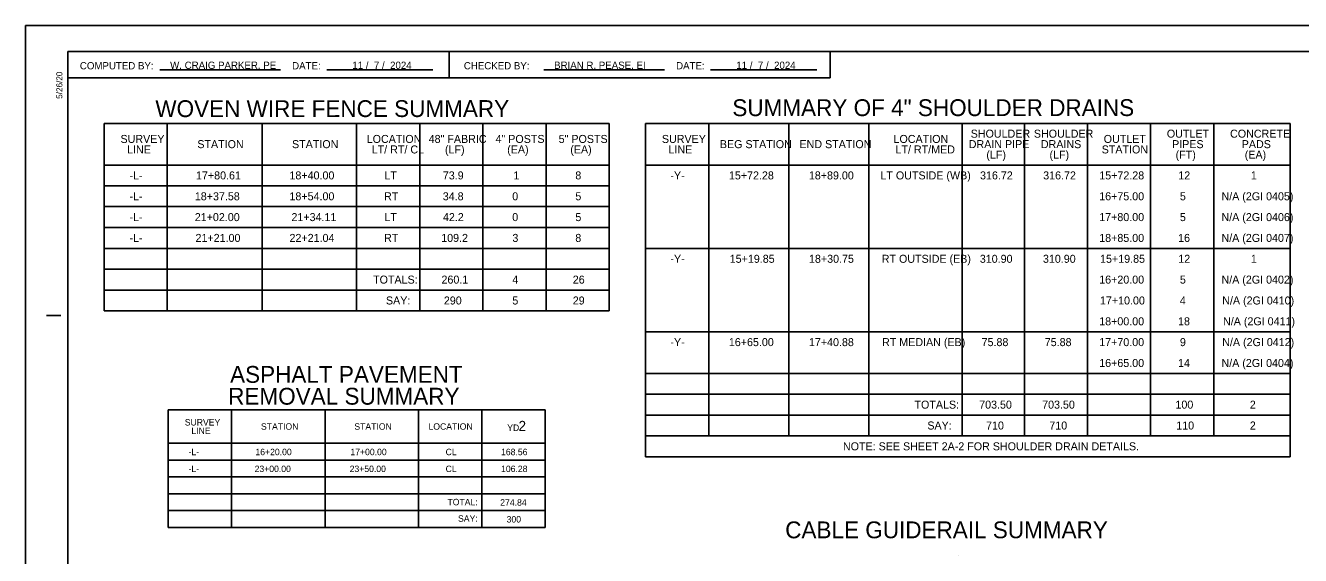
# Model space of a CAD drawing. Extents: x 1551694 to 1553358, y 810412 to 811095.
# Drawn here: x 1552983.2 to 1553203.1, y 810610.5 to 810701.9 of the extents above; entities that cross this region are included whole.
import ezdxf

# ---------------------------------------------------------------- set-up
doc = ezdxf.new("R2010")
doc.units = 0
for name, color, linetype in [('Construction Elements LEVEL', 7, 'Continuous'), ('Default', 7, 'Continuous'), ('Drop Inlet Grate 2 Narrow Slot and Flat Grates 840 29 36 Dia BD-Top CELL', 7, 'Continuous'), ('Drop Inlet Grate 2 Narrow Slot and Flat Grates 840 29 36 Dia TB-Top CELL', 7, 'Continuous'), ('E_NCDOT_Vertical_Profile_Ground_Line', 7, 'Continuous'), ('P_HYD_Pipe_RCP_15in_Class_III', 7, 'Continuous'), ('V Ditch Special Lateral with PSRM Detail CELL', 7, 'Continuous')]:
    doc.layers.add(name, color=color, linetype=linetype)

msp = doc.modelspace()

# ---------------------------------------------------------------- linework, layer by layer
at = {"layer": 'Construction Elements LEVEL'}
for p, q in [((1552996.77, 810685.06), (1553083.88, 810685.06)), ((1552996.77, 810685.06), (1552996.77, 810652.72)), ((1553007.66, 810685.06), (1553007.66, 810652.72)), ((1553024, 810685.06), (1553024, 810652.72)), ((1553040.32, 810685.06), (1553040.32, 810652.72)), ((1553051.21, 810685.06), (1553051.21, 810652.72)), ((1553062.1, 810685.06), (1553062.1, 810652.72)), ((1553072.99, 810685.06), (1553072.99, 810652.72)), ((1553083.88, 810685.06), (1553083.88, 810652.72)), ((1553090.15, 810685.06), (1553201.33, 810685.06)), ((1553090.15, 810685.06), (1553090.15, 810627.56)), ((1553101.04, 810685.06), (1553101.04, 810631.15)), ((1553114.84, 810685.06), (1553114.84, 810631.15)), ((1553128.64, 810685.06), (1553128.64, 810631.15)), ((1553144.74, 810685.06), (1553144.74, 810631.15)), ((1553155.47, 810685.06), (1553155.47, 810631.15)), ((1553166.36, 810685.06), (1553166.36, 810631.15)), ((1553177.25, 810685.06), (1553177.25, 810631.15)), ((1553188.14, 810685.06), (1553188.14, 810631.15)), ((1553201.33, 810685.06), (1553201.33, 810627.56)), ((1552996.77, 810677.87), (1553083.88, 810677.87)), ((1553090.15, 810677.87), (1553201.33, 810677.87)), ((1552996.77, 810674.28), (1553083.88, 810674.28)), ((1552996.77, 810670.69), (1553083.88, 810670.69)), ((1552996.77, 810670.69), (1553083.88, 810670.69)), ((1552996.77, 810667.09), (1553083.88, 810667.09)), ((1552996.77, 810663.5), (1553083.88, 810663.5)), ((1553090.15, 810663.5), (1553201.33, 810663.5)), ((1553090.15, 810663.5), (1553201.33, 810663.5)), ((1552996.77, 810659.9), (1553083.88, 810659.9)), ((1552996.77, 810656.31), (1553083.88, 810656.31)), ((1552996.77, 810652.72), (1553083.88, 810652.72)), ((1552996.77, 810652.72), (1553083.88, 810652.72)), ((1553090.15, 810649.12), (1553201.33, 810649.12)), ((1553090.15, 810641.94), (1553201.33, 810641.94)), ((1553090.15, 810638.34), (1553201.33, 810638.34)), ((1553007.84, 810635.68), (1553072.81, 810635.68)), ((1553007.84, 810635.68), (1553007.84, 810615.37)), ((1553018.76, 810635.68), (1553018.76, 810615.37)), ((1553034.86, 810635.68), (1553034.86, 810615.37)), ((1553050.96, 810635.68), (1553050.96, 810615.37)), ((1553061.89, 810635.68), (1553061.89, 810615.37)), ((1553072.81, 810635.68), (1553072.81, 810615.37)), ((1553090.15, 810634.75), (1553201.33, 810634.75)), ((1553007.84, 810629.88), (1553072.81, 810629.88)), ((1553090.15, 810631.15), (1553201.33, 810631.15)), ((1553090.15, 810627.56), (1553201.33, 810627.56)), ((1553007.84, 810626.98), (1553072.81, 810626.98)), ((1553007.84, 810624.07), (1553072.81, 810624.07)), ((1553007.84, 810621.17), (1553072.81, 810621.17)), ((1553007.84, 810618.27), (1553072.81, 810618.27)), ((1553007.84, 810615.37), (1553072.81, 810615.37))]:
    msp.add_line(p, q, dxfattribs=at)
at = {"layer": 'Drop Inlet Grate 2 Narrow Slot and Flat Grates 840 29 36 Dia TB-Top CELL'}
for p, q in [((1553056.25, 810692.88), (1553056.25, 810697.43)), ((1553122.01, 810692.88), (1553122.01, 810697.43)), ((1553006.39, 810694.26), (1553027.21, 810694.26)), ((1553035.15, 810694.26), (1553053.44, 810694.26)), ((1553072.61, 810694.26), (1553093.43, 810694.26)), ((1553101.37, 810694.26), (1553119.66, 810694.26)), ((1553122.01, 810692.88), (1552990.5, 810692.88))]:
    msp.add_line(p, q, dxfattribs=at)
at = {"layer": 'E_NCDOT_Vertical_Profile_Ground_Line'}
for p, q in [((1553029.57, 810685.05), (1553029.57, 810685.05)), ((1553031.02, 810685.02), (1553031.02, 810685.02)), ((1553033.12, 810685.08), (1553033.12, 810685.08)), ((1553034.42, 810685.05), (1553034.42, 810685.05)), ((1553040.63, 810635.67), (1553040.63, 810635.67)), ((1553042.08, 810635.65), (1553042.08, 810635.65)), ((1553044.19, 810635.69), (1553044.19, 810635.69)), ((1553045.49, 810635.67), (1553045.49, 810635.67)), ((1553144.14, 810610.54), (1553144.14, 810610.54))]:
    msp.add_line(p, q, dxfattribs=at)
at = {"layer": 'P_HYD_Pipe_RCP_15in_Class_III'}
for p, q in [((1552990.5, 810486.43), (1552990.5, 810697.43)), ((1553320.5, 810697.43), (1552990.5, 810697.43)), ((1552986.8, 810651.93), (1552989.31, 810651.94))]:
    msp.add_line(p, q, dxfattribs=at)
at = {"layer": 'V Ditch Special Lateral with PSRM Detail CELL'}
for p, q in [((1553323.21, 810701.93), (1552983.21, 810701.93)), ((1552983.21, 810701.93), (1552983.21, 810481.93))]:
    msp.add_line(p, q, dxfattribs=at)

# ---------------------------------------------------------------- texts
at = {"layer": 'Construction Elements LEVEL'}
for s, height, p in [('YD', 1.114, (1553066.29, 810632.01)), ('2', 1.74, (1553068.24, 810632.01))]:
    msp.add_text(s, height=height, dxfattribs=at).set_placement(p)
at = {"layer": 'Default'}
for s, p in [('-L-', (1553001.14, 810675.39)), ('17+80.61', (1553012.61, 810675.39)), ('18+40.00', (1553028.73, 810675.39)), ('LT', (1553045.11, 810675.39)), ('73.9', (1553055.18, 810675.39)), ('1', (1553067.36, 810675.39)), ('8', (1553078.03, 810675.39)), ('-Y-', (1553094.43, 810675.39)), ('15+72.28', (1553104.52, 810675.39)), ('18+89.00', (1553118.31, 810675.39)), ('LT OUTSIDE (WB)', (1553130.65, 810675.39)), ('316.72', (1553147.83, 810675.39)), ('316.72', (1553158.72, 810675.39)), ('15+72.28', (1553168.39, 810675.39)), ('12', (1553182.02, 810675.39)), ('1', (1553194.53, 810675.39)), ('-L-', (1553001.14, 810671.79)), ('18+37.58', (1553012.41, 810671.79)), ('18+54.00', (1553028.73, 810671.79)), ('RT', (1553045.04, 810671.79)), ('34.8', (1553055.17, 810671.79)), ('0', (1553067.15, 810671.79)), ('5', (1553078.04, 810671.79)), ('16+75.00', (1553168.38, 810671.79)), ('5', (1553182.3, 810671.79)), ('N/A (2GI 0405)', (1553189.47, 810671.79)), ('-L-', (1553001.14, 810668.2)), ('21+02.00', (1553012.4, 810668.2)), ('21+34.11', (1553029.07, 810668.2)), ('LT', (1553045.11, 810668.2)), ('42.2', (1553055.2, 810668.2)), ('0', (1553067.15, 810668.2)), ('5', (1553078.04, 810668.2)), ('17+80.00', (1553168.38, 810668.2)), ('5', (1553182.3, 810668.2)), ('N/A (2GI 0406)', (1553189.47, 810668.2)), ('-L-', (1553001.14, 810664.61)), ('21+21.00', (1553012.53, 810664.61)), ('22+21.04', (1553028.74, 810664.61)), ('RT', (1553045.04, 810664.61)), ('109.2', (1553054.9, 810664.61)), ('3', (1553067.18, 810664.61)), ('8', (1553078.03, 810664.61)), ('18+85.00', (1553168.38, 810664.61)), ('16', (1553181.99, 810664.61)), ('N/A (2GI 0407)', (1553189.47, 810664.61)), ('-Y-', (1553094.43, 810661.01)), ('15+19.85', (1553104.66, 810661.01)), ('18+30.75', (1553118.33, 810661.01)), ('RT OUTSIDE (EB)', (1553130.88, 810661.01)), ('310.90', (1553147.79, 810661.01)), ('310.90', (1553158.68, 810661.01)), ('15+19.85', (1553168.53, 810661.01)), ('12', (1553182.02, 810661.01)), ('1', (1553194.53, 810661.01)), ('260.1', (1553054.95, 810657.42)), ('4', (1553067.16, 810657.42)), ('26', (1553077.59, 810657.42)), ('16+20.00', (1553168.38, 810657.42)), ('5', (1553182.3, 810657.42)), ('N/A (2GI 0402)', (1553189.47, 810657.42)), ('290', (1553055.36, 810653.82)), ('5', (1553067.17, 810653.82)), ('29', (1553077.59, 810653.82)), ('17+10.00', (1553168.51, 810653.82)), ('4', (1553182.29, 810653.82)), ('N/A (2GI 0410)', (1553189.6, 810653.82)), ('N/A (2GI 0411)', (1553189.74, 810650.23)), ('18+00.00', (1553168.38, 810650.23)), ('18', (1553181.98, 810650.23)), ('-Y-', (1553094.43, 810646.64)), ('16+65.00', (1553104.51, 810646.64)), ('17+40.88', (1553118.32, 810646.64)), ('RT MEDIAN (EB)', (1553130.93, 810646.64)), ('75.88', (1553148.1, 810646.64)), ('75.88', (1553158.99, 810646.64)), ('17+70.00', (1553168.38, 810646.64)), ('9', (1553182.3, 810646.64)), ('N/A (2GI 0412)', (1553189.6, 810646.64)), ('16+65.00', (1553168.38, 810643.04)), ('14', (1553181.98, 810643.04)), ('N/A (2GI 0404)', (1553189.47, 810643.04)), ('703.50', (1553147.68, 810635.86)), ('703.50', (1553158.54, 810635.86)), ('100', (1553181.53, 810635.86)), ('2', (1553194.36, 810635.86)), ('710', (1553148.87, 810632.26)), ('710', (1553159.78, 810632.26)), ('110', (1553181.67, 810632.26)), ('2', (1553194.36, 810632.26))]:
    msp.add_text(s, height=1.38, rotation=360, dxfattribs=at).set_placement(p)
at = {"layer": 'Drop Inlet Grate 2 Narrow Slot and Flat Grates 840 29 36 Dia BD-Top CELL'}
for s, p in [('W. CRAIG PARKER, PE', (1553008.15, 810694.45)), ('BRIAN R. PEASE, EI', (1553074.37, 810694.45)), ('COMPUTED BY:', (1552992.58, 810694.37)), ('DATE:', (1553029.19, 810694.37)), ('CHECKED BY:', (1553058.8, 810694.37)), ('DATE:', (1553095.41, 810694.37))]:
    msp.add_text(s, height=1.25, dxfattribs=at).set_placement(p)
at = {"layer": 'E_NCDOT_Vertical_Profile_Ground_Line'}
for s, height, p in [('11 /  7 /  2024', 1.25, (1553039.58, 810694.45)), ('11 /  7 /  2024', 1.25, (1553105.8, 810694.45)), ('SURVEY', 1.114, (1553010.67, 810632.95)), ('LINE', 1.114, (1553011.81, 810631.49)), ('STATION', 1.114, (1553023.82, 810632.22)), ('STATION', 1.114, (1553039.92, 810632.22)), ('LOCATION', 1.114, (1553052.71, 810632.22)), ('-L-', 1.114, (1553011.33, 810627.83)), ('16+20.00', 1.114, (1553022.86, 810627.83)), ('17+00.00', 1.114, (1553039.24, 810627.83)), ('CL', 1.114, (1553055.66, 810627.83)), ('168.56', 1.114, (1553065.22, 810627.83)), ('-L-', 1.114, (1553011.33, 810624.92)), ('23+00.00', 1.114, (1553022.72, 810624.92)), ('23+50.00', 1.114, (1553039.11, 810624.92)), ('CL', 1.114, (1553055.66, 810624.92)), ('106.28', 1.114, (1553065.22, 810624.92)), ('TOTAL:', 1.114, (1553055.98, 810619.19)), ('274.84', 1.114, (1553065.08, 810619.12)), ('SAY:', 1.114, (1553057.8, 810616.35)), ('300', 1.114, (1553066.18, 810616.22))]:
    msp.add_text(s, height=height, dxfattribs=at).set_placement(p)
for s, height, rotation, p in [('WOVEN WIRE FENCE SUMMARY', 2.9023, 0.0148, (1553005.6, 810686.14)), ('SUMMARY OF 4" SHOULDER DRAINS', 2.9023, 0.0148, (1553105.11, 810686.3)), ('SURVEY', 1.38, 360, (1552999.59, 810681.68)), ('LOCATION', 1.38, 360, (1553042.05, 810681.68)), ('48" FABRIC', 1.38, 360, (1553052.74, 810681.68)), ('4" POSTS', 1.38, 360, (1553064.27, 810681.68)), ('5" POSTS', 1.38, 360, (1553075.16, 810681.68)), ('SURVEY', 1.38, 360, (1553092.96, 810681.68)), ('LOCATION', 1.38, 360, (1553132.91, 810681.68)), ('SHOULDER', 1.38, 360, (1553146.22, 810682.59)), ('SHOULDER', 1.38, 360, (1553157.11, 810682.59)), ('OUTLET', 1.38, 360, (1553169.16, 810681.68)), ('OUTLET', 1.38, 360, (1553180.05, 810682.59)), ('CONCRETE', 1.38, 360, (1553190.95, 810682.59)), ('LINE', 1.38, 360, (1553000.73, 810679.87)), ('STATION', 1.38, 360, (1553012.84, 810680.78)), ('STATION', 1.38, 360, (1553029.17, 810680.78)), ('LT/ RT/ CL', 1.38, 360, (1553042.92, 810679.87)), ('(LF)', 1.38, 360, (1553055.55, 810679.87)), ('(EA)', 1.38, 360, (1553066.28, 810679.87)), ('(EA)', 1.38, 360, (1553077.16, 810679.87)), ('LINE', 1.38, 360, (1553094.1, 810679.87)), ('BEG STATION', 1.38, 360, (1553102.96, 810680.78)), ('END STATION', 1.38, 360, (1553116.69, 810680.78)), ('LT/ RT/MED', 1.38, 360, (1553133.25, 810679.87)), ('DRAIN PIPE', 1.38, 360, (1553145.88, 810680.78)), ('(LF)', 1.38, 360, (1553148.92, 810678.97)), ('DRAINS', 1.38, 360, (1553158.32, 810680.78)), ('(LF)', 1.38, 360, (1553159.81, 810678.97)), ('STATION', 1.38, 360, (1553168.81, 810679.87)), ('PIPES', 1.38, 360, (1553180.95, 810680.78)), ('(FT)', 1.38, 360, (1553181.56, 810678.97)), ('PADS', 1.38, 360, (1553192.96, 810680.78)), ('(EA)', 1.38, 360, (1553193.48, 810678.97)), ('TOTALS:', 1.38, 360, (1553043.15, 810657.42)), ('SAY:', 1.38, 360, (1553045.37, 810653.82)), ('ASPHALT PAVEMENT', 2.9023, 0.0119, (1553018.49, 810640.31)), ('REMOVAL SUMMARY', 2.9023, 0.0119, (1553018.16, 810636.54)), ('TOTALS:', 1.38, 360, (1553136.52, 810635.86)), ('SAY:', 1.38, 360, (1553138.74, 810632.26)), ('NOTE: SEE SHEET 2A-2 FOR SHOULDER DRAIN DETAILS.', 1.38, 360, (1553124.19, 810628.67)), ('CABLE GUIDERAIL SUMMARY', 2.9023, 0.0119, (1553114.23, 810613.5))]:
    msp.add_text(s, height=height, rotation=rotation, dxfattribs=at).set_placement(p)
at = {"layer": 'P_HYD_Pipe_RCP_15in_Class_III'}
msp.add_text('5/26/20', height=1.05, rotation=90, dxfattribs=at).set_placement((1552989.57, 810689.29))

doc.saveas('drawing.dxf')
